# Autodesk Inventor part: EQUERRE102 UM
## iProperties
Created: 2001-03
Part Number: EQUERRE102 UM
Material: Acier doux
Document SubType Name: Tôlerie
Designer: jost
Control State: 0
Master: False
Checked Out: False
Shininess: 41.0
Length Units: 11269
Angle Units: 11279
Time Units: 11290
Mass Units: 11283
Length Display Precision: 3
Angle Display Precision: 2
Density: 7.86
Volumn: 4.072681723638398
Area: 34.37946555829247
PropertySet Name: Model Information
Author: jost
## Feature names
1. Perçage1 [Hole]
2. Perçage2 [Hole]
3. Plaque1
4. Plaque2
5. Pli1
